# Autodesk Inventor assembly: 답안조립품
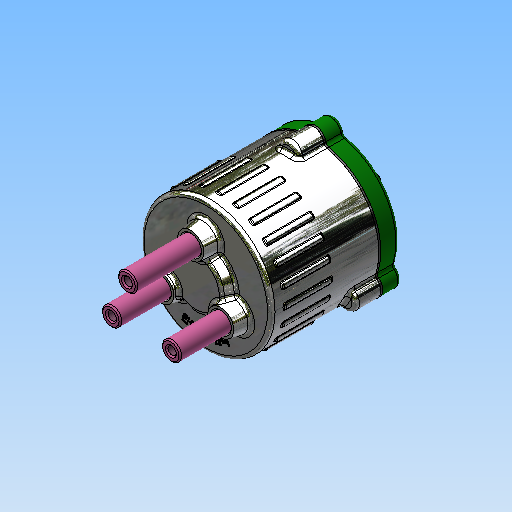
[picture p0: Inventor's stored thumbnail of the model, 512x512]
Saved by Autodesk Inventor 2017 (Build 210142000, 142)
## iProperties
Part Number: 답안조립품
Material: 일반
Document SubType Name: Assembly
Designer: MRC
Author: MRC
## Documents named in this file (15)
- C:\Users\MRC\Desktop\620811V1004\답안조립품.iam
- C:\Users\MRC\Desktop\620811V1004\본체.ipt
- C:\Users\MRC\Desktop\620811V1004\가변스프링1.ipt
- C:\Users\MRC\Desktop\620811V1004\가변스프링2.ipt
- C:\Users\MRC\Desktop\620811V1004\가변스프링3.ipt
- C:\Users\MRC\Desktop\620811V1004\개스킷.ipt
- C:\Users\MRC\Desktop\620811V1004\멈춤링 10x1.ipt
- C:\Users\MRC\Desktop\620811V1004\멈춤링 22x1.2.ipt
- C:\Users\MRC\Desktop\620811V1004\메인 축.ipt
- C:\Users\MRC\Desktop\620811V1004\베어링 NA 4900.ipt
- C:\Users\MRC\Desktop\620811V1004\볼트 M5.ipt
- C:\Users\MRC\Desktop\620811V1004\슬라이드 축.ipt
- C:\Users\MRC\Desktop\620811V1004\오일 실.ipt
- C:\Users\MRC\Desktop\620811V1004\커버.ipt
- C:\Users\MRC\Desktop\620811V1004\판캠.ipt
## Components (4 placed, 4 different names)
1. 가변스프링1:1
2. 가변스프링2:1
3. 가변스프링3:1
4. 개스킷:1
